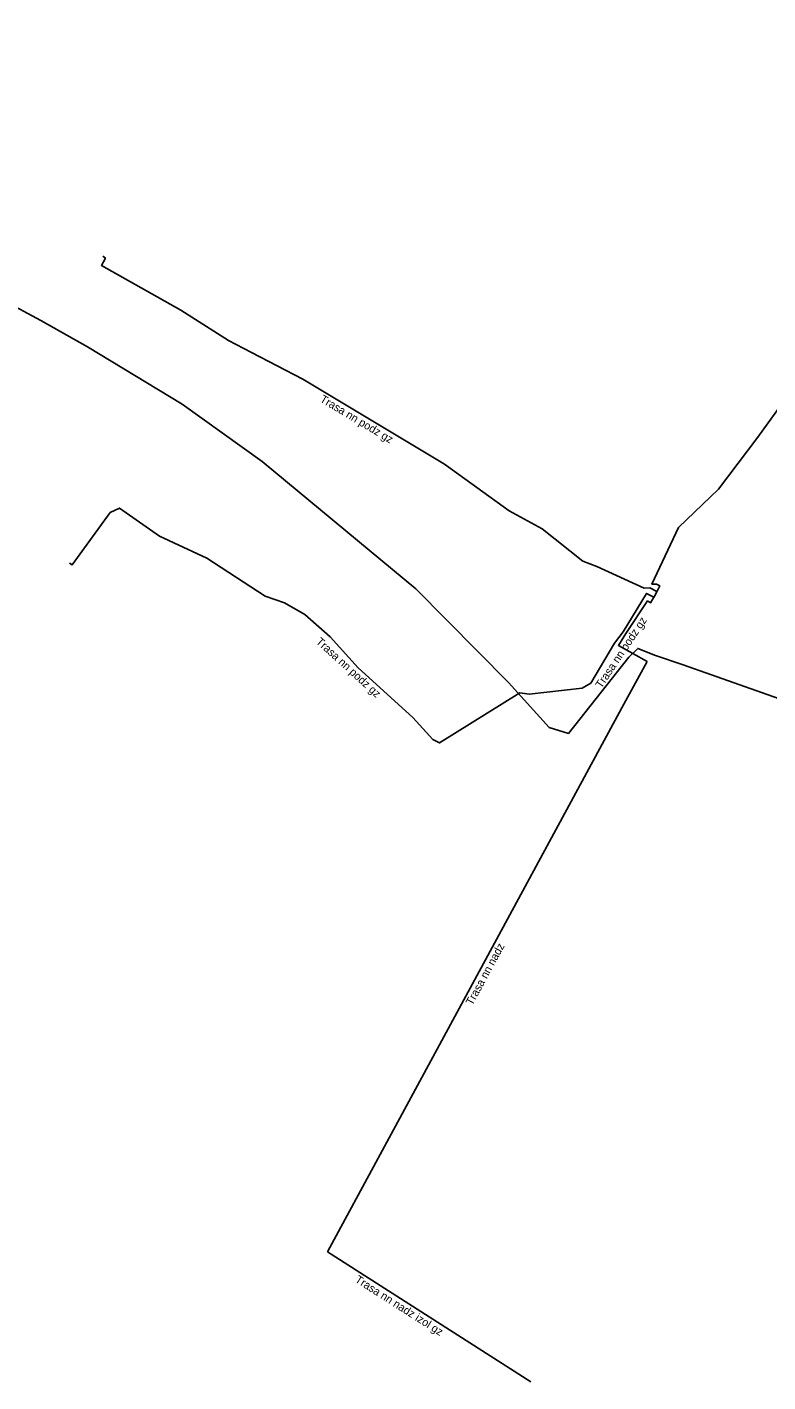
# Model space of a CAD drawing. Extents: x -686919 to -686577, y -972514 to -971911.
# Drawn here: x -686790.9 to -686744.6, y -972263.6 to -972179 of the extents above; entities that cross this region are included whole.
import ezdxf

# ---------------------------------------------------------------- set-up
doc = ezdxf.new("R2010")
doc.units = 0
for name, color, linetype in [('Popiskový text - Ostatní atributy Trasy', 7, 'Continuous'), ('Spojnice NN', 7, 'Continuous'), ('Spojnice VN', 7, 'Continuous')]:
    doc.layers.add(name, color=color, linetype=linetype)

msp = doc.modelspace()

# ---------------------------------------------------------------- linework, layer by layer
at = {"layer": 'Spojnice NN'}
for points in [[(-686717.01, -972186.11), (-686717.135, -972186.266), (-686724.274, -972180.515), (-686726.62, -972178.96), (-686727.05, -972179.17), (-686727.784, -972180.303), (-686728.55, -972181.41), (-686733.03, -972187.11), (-686734.41, -972189.1), (-686737.8, -972193.81), (-686740.28, -972197.68), (-686745.27, -972204.58), (-686747.73, -972207.84), (-686750.23, -972210.23), (-686751.88, -972213.78), (-686751.602, -972213.769), (-686751.387, -972213.881), (-686751.67, -972214.41)], [(-686751.67, -972214.41), (-686751.576, -972214.234), (-686752.024, -972213.994), (-686752.36, -972214.03), (-686755.32, -972212.66), (-686756.2, -972212.33), (-686758.75, -972210.31), (-686760.8, -972209.18), (-686764.85, -972206.27), (-686773.7, -972200.97), (-686776.91, -972199.3), (-686778.355, -972198.535), (-686781.33, -972196.64), (-686786.293, -972193.854), (-686786.044, -972193.393), (-686786.21, -972193.28)], [(-686788.29, -972212.45), (-686788.121, -972212.56), (-686785.741, -972209.289), (-686785.17, -972209.02), (-686782.66, -972210.78), (-686779.71, -972212.15), (-686776.05, -972214.53), (-686774.85, -972214.94), (-686773.57, -972215.66), (-686771.99, -972217.06), (-686770.24, -972218.99), (-686766.83, -972222.1), (-686765.57, -972223.47), (-686765.16, -972223.69), (-686760.14, -972220.56), (-686759.55, -972220.65), (-686756.24, -972220.27), (-686755.71, -972219.95), (-686754.214, -972217.447), (-686753.68, -972216.75), (-686752.212, -972214.346), (-686751.768, -972214.585), (-686751.67, -972214.41)], [(-686752.19, -972218.61), (-686753.979, -972217.594), (-686753.507, -972216.85), (-686752.156, -972214.821), (-686751.967, -972214.929), (-686751.67, -972214.41)], [(-686752.19, -972218.61), (-686753.765, -972221.504), (-686772.17, -972255.5)], [(-686772.17, -972255.5), (-686759.45, -972263.62)]]:
    msp.add_lwpolyline(points, dxfattribs=at)
at = {"layer": 'Spojnice VN'}
msp.add_lwpolyline([(-686797.29, -972193.43), (-686790.08, -972197.29), (-686787.17, -972198.94), (-686781.25, -972202.53), (-686776.24, -972206.1), (-686766.65, -972214.07), (-686760.84, -972219.91), (-686758.31, -972222.72), (-686757.1, -972223.1), (-686753.32, -972218.34), (-686752.77, -972217.79), (-686751.65, -972218.22), (-686749.93, -972218.81), (-686742.56, -972221.41), (-686740.79, -972221.22), (-686735.88, -972212.38), (-686732.08, -972206.19)], dxfattribs=at)

# ---------------------------------------------------------------- texts
at = {"layer": 'Popiskový text - Ostatní atributy Trasy'}
for s, rotation, p in [('Trasa nn podz gz', 329.08387, (-686772.679, -972202.339)), ('Trasa nn podz gz', 56.34253, (-686755.037, -972220.321)), ('Trasa nn podz gz', 317.63445, (-686772.924, -972217.421)), ('Trasa nn nadz', 61.56877, (-686763.11, -972240.131)), ('Trasa nn nadz izol gz', 327.44727, (-686770.488, -972257.344))]:
    msp.add_text(s, height=0.5, rotation=rotation, dxfattribs=at).set_placement(p)

doc.saveas('drawing.dxf')
